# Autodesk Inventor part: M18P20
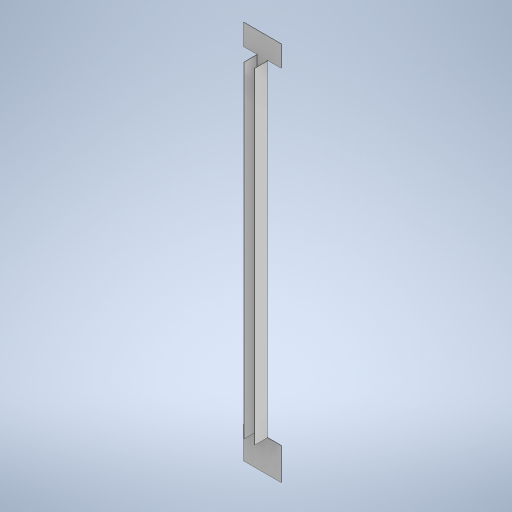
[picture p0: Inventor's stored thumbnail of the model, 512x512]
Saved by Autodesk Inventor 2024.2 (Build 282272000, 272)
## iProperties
Created: 2024-05
Part Number: M18P20
Material: Generic
Document SubType Name: Sheet Metal
Designer: Olivier St-Arneault
Density: 1 g/cm^3
Sheet Metal Rule: Default
Appearance: Default
Author: Olivier St-Arneault
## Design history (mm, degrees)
node "Face1"
  sketch "Sketch1"
    geometry: L1 (-26.987, 273.05)-(-26.987, 242.887); L2 (-26.987, 273.05)-(26.988, 273.05); L3 (26.988, 273.05)-(26.988, 242.887); L4 (26.988, 242.887)-(7.938, 242.887); L5 (-26.987, 242.887)-(-7.937, 242.887); L6 (-7.937, 242.887)-(-7.937, 242.475); L7 (7.938, 242.887)-(7.938, 242.475); L8 (-7.937, -226.6)-(-7.937, -227.013); L9 (-7.937, -227.013)-(-26.987, -227.013); L10 (7.938, -226.6)-(7.938, -227.013); L11 (7.938, -227.013)-(26.988, -227.013); L12 (-26.987, -227.013)-(-26.987, -273.05); L13 (-26.987, -273.05)-(26.988, -273.05); L14 (26.988, -273.05)-(26.988, -227.013); L15 (-39.175, 0)-(65.281, 0); L16 (0, 44.939)-(0, -395.251); L17 (-7.937, 242.475)-(-7.937, -226.6); L18 (7.938, -226.6)-(7.938, 242.475); 1 further point
    constraints: 36 end point, 6 vertical, 5 perpendicular, 3 horizontal, 2 collinear, 2 point on line, 1 other
    dimensions: "d0" = 30.1625 distance of L1.start L1.end; "d1" = 53.975 distance of L1.start L2.end; "d2" = 19.05 distance of L1.end L5.end; "d3" = 0.41275 distance of L5.end L6.end; "d7" = 0.41275 distance of L8.start L8.end; "d10" = 0.41275 distance of L10.start L10.end; "d11" = 546.1 distance between parallel lines of L2 L13; "d12" = 30.1625 distance between parallel lines of L4 L2; "d14" = 19.05 distance of L3.end L4.end; "d26" = 469.9 distance between parallel lines of L4 L11
node "Flange1"
body "Solid1"
face "Plate1" dims "d15" = 0.508 (= Thickness)
sketch "Sketch3"
  geometry: L1 (-469.392, 0)-(-0.508, 0); L2 (-0.508, 0)-(-0.508, 19.05); L3 (-0.508, 19.05)-(-469.392, 19.05); L4 (-469.392, 19.05)-(-469.392, 0)
  constraints: 8 end point
face "Plate2" dims "d15" = 0.508 (= Thickness), "d16" = 0.508 (= BendReliefWidth), "d17" = 0.254 (= BendReliefDepth), "d18" = 1.016 (= MinimumRemnant), "d19" = 0.508 (= TransitionRadius), "d20" = 19.05, "d21" = 90 deg, "d22" = 0.508 (= BendRadius), "d23" = 2.032 (= CornerReliefSize), "d24" = 0.508 (= GapSize), "d25" = 0.508 (= JacobiRadiusSize), "SeamGap" = 0.00508
bend "Bend1" dims "d15" = 0.508 (= Thickness), "d16" = 0.508 (= BendReliefWidth), "d17" = 0.254 (= BendReliefDepth), "d18" = 1.016 (= MinimumRemnant), "d19" = 0.508 (= TransitionRadius), "d20" = 19.05, "d21" = 90 deg, "d22" = 0.508 (= BendRadius), "SeamGap" = 0.00508
feature "Corner1" dims "d20" = 19.05, "d21" = 90 deg, "d23" = 2.032 (= CornerReliefSize), "d24" = 0.508 (= GapSize), "d25" = 0.508 (= JacobiRadiusSize)
other parameters: "Thickness" = 0.508 (derived), "BendRadius" = 0.508 (= Thickness), "BendReliefWidth" = 0.508 (= Thickness), "BendReliefDepth" = 0.254 (= 0.5 x Thickness), "CornerReliefSize" = 2.032 (= 4 x Thickness), "MinimumRemnant" = 1.016 (= 2 x Thickness), "TransitionRadius" = 0.508 (= BendRadius), "JacobiRadiusSize" = 0.508 (= BendRadius), "GapSize" = 0.508 (= Thickness)
